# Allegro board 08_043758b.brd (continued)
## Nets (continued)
GND: C1.2(N2) C2.2(N2) C3.2(N2) C4.2(N2) C5.2(N2) C6.2(N2) C7.1(N1) C8.2(N2) C9.2(N2) C10.2(N2) C11.2(N2) C12.2(N2) C13.2(N2) C14.2(N2) C15.2(N2) C16.2(N2) C17.2(N2) C18.2(N2) C19.2(N2) C20.2(N2) C21.2(N2) C22.2(N2) C23.2(N2) C24.2(N2) C25.2(N2) C26.2(N2) C27.2(N2) C28.2(N2) C29.2(N2) C30.2(N2) C31.2(N2) C32.2(N2) C33.2(N2) C34.2(N2) C35.2(N2) C36.2(N2) C37.2(N2) C38.2(N2) C39.2(N2) C40.2(N2) C41.2(N2) C42.2(N2) C43.2(N2) C44.2(N2) C45.2(N2) C46.2(N2) C47.2(N2) C48.2(N2) C49.2(N2) C50.2(N2) C51.2(N2) C52.2(N2) C53.2(N2) C54.2(N2) C55.2(N2) C56.2(N2) C57.2(N2) C58.2(N2) C59.2(N2) C60.2(N2) C61.2(N2) C62.1(N1) C63.1(N1) C64.2(N2) C65.2(N2) C66.2(N2) C67.2(N2) C68.2(N2) C69.2(N2) C70.2(N2) C71.2(N2) C72.2(N2) C73.2(N2) C74.2(N2) C75.2(N2) C76.2(N2) C77.2(N2) C78.2(N2) C79.2(N2) C80.2(N2) C81.2(N2) C82.2(N2) C83.2(N2) C84.2(N2) C85.2(N2) C86.2(N2) C87.2(N2) C88.2(N2) C89.2(N2) C90.2(N2) C91.2(N2) C92.2(N2) C94.2(N2) C95.2(N2) C96.2(N2) C97.2(N2) C99.1(N1) C100.2(N2) C101.2(N2) C102.2(N2) C103.2(N2) C104.2(N2) C105.2(N2) C106.2(N2) C107.2(N2) C108.2(N2) C109.2(N2) C110.2(N2) C111.2(N2) C112.2(N2) C113.2(N2) C114.2(N2) C115.2(N2) C116.2(N2) C117.2(N2) C118.2(N2) C119.2(N2) C120.2(N2) C121.2(N2) C122.2(N2) C124.2(N2) C125.1(N1) C126.1(N1) C127.2(N2) C128.2(N2) C129.1(N1) C130.2(N2) C135.2(N2) C136.2(N2) C137.2(N2) C138.2(N2) C139.1(N1) C140.2(N2) C141.2(N2) C142.1(N1) C143.1(N1) C145.2(N2) C146.2(N2) C147.1(N1) C148.2(N2) C149.2(N2) C150.2(N2) C151.2(N2) C152.2(N2) C153.2(N2) C154.2(N2) C155.2(N2) C156.2(N2) C157.2(N2) C158.2(N2) C159.2(N2) C160.2(N2) C161.2(N2) C162.2(N2) C163.1(N1) C164.2(N2) C165.2(N2) C166.1(N1) C167.2(N2) C168.2(N2) C169.2(N2) C170.2(N2) C173.2(N2) C174.2(N2) C178.2(N2) D1.A(P) D2.A(P) D3.A(P) E6.1(N1) GND.1 GND#2.1 GND#3.1 GND#4.1 L7.3(N3) P1.7(N4) P1.9(N5) Q1.2(S) Q4.2(S) R2.1(N1) R3.1(N1) R9.2(N2) R15.2(N2) R40.2(N2) R42.2(N2) R49.1(N1) R53.1(N1) R54.2(N2) R61.1(N1) R63.2(N2) R65.1(N1) R72.2(N2) R75.2(N2) R77.2(N2) R90.2(N2) R91.2(N2) R116.2(N2) R119.2(N2) R120.2(N2) R121.2(N2) R165.2(N2) RX1A.2(SH1) RX1A.3(SH2) RX1A.4(SH3) RX1A.5(SH4) S1.3(N3) S1.4(N4) T1.1(NC1) T1.2(PRI) T1.5(NC2) T5.1(NC1) T5.2(PRI) T5.5(NC2) TX1A.2(SH1) TX1A.3(SH2) TX1A.4(SH3) TX1A.5(SH4) U1.6(GND) U1.PAD U2.A9(VSS_1) U2.B1(VSSQ_1) U2.B3(VSS_2) U2.B9(VSSQ_2) U2.D1(VSSQ_3) U2.D8(VSSQ_4) U2.E1(VSS_3) U2.E2(VSSQ_5) U2.E8(VSSQ_6) U2.F9(VSSQ_7) U2.G1(VSSQ_8) U2.G8(VSS_4) U2.G9(VSSQ_9) U2.J2(VSS_5) U2.J8(VSS_6) U2.M1(VSS_7) U2.M9(VSS_8) U2.P1(VSS_9) U2.P9(VSS_10) U2.T1(VSS_11) U2.T9(VSS_12) U3.5(GND) U3.6(PGND_1) U3.7(PGND_2) U3.8(PGND_3) U3.PAD U4.A1(GND_1) U4.A11(GND_2) U4.B8(GND_3) U4.C5(GND_4) U4.C15(GND_5) U4.D2(GND_6) U4.D12(GND_7) U4.E5(GND_8) U4.E7(GND_9) U4.E8(RSVDGND) U4.E9(GND_10) U4.F10(GND_11) U4.G3(GND_12) U4.G5(GND_13) U4.G13(GND_14) U4.H6(GND_15) U4.H8(VN_0) U4.H10(GND_16) U4.J5(GND_17) U4.J9(GND_18) U4.K4(GND_19) U4.K7(GND_20) U4.K10(GND_21) U4.K14(GND_22) U4.L1(GND_23) U4.L5(GND_24) U4.L11(GND_25) U4.M8(GND_26) U4.N5(GND_27) U4.N15(GND_28) U4.P2(GND_29) U4.P12(GND_30) U4.R9(GND_31) U5.A1(RX2A_N) U5.A2(RX2A_P) U5.A4(VSSA_1) U5.A5(TX_MON2) U5.A6(VSSA_2) U5.A12(VSSA_3) U5.B1(VSSA_4) U5.B2(VSSA_5) U5.B12(VSSA_6) U5.C1(RX2C_P) U5.C2(VSSA_7) U5.C4(TEST/ENABLE) U5.C7(VSSA_8) U5.C8(VSSA_9) U5.C9(VSSA_10) U5.C10(VSSA_11) U5.C11(VSSA_12) U5.C12(VSSA_13) U5.D1(RX2C_N) U5.D12(VSSD_1) U5.E1(RX2B_P) U5.F1(RX2B_N) U5.F3(VSSA_14) U5.F7(VSSD_2) U5.F9(VSSD_3) U5.F11(VSSD_4) U5.G1(VSSA_15) U5.G10(FB_CLK_N) U5.G12(VSSD_5) U5.H1(RX1B_P) U5.H2(VSSA_16) U5.H3(VSSA_17) U5.H5(VSSA_18) U5.H6(VSSA_19) U5.H7(VSSD_6) U5.H9(TX_FRAME_N) U5.H10(VSSD_7) U5.J1(RX1B_N) U5.J2(VSSA_20) U5.K1(RX1C_P) U5.K2(VSSA_21) U5.K12(VSSD_8) U5.L1(RX1C_N) U5.L2(VSSA_22) U5.L3(VSSA_23) U5.L7(VSSA_24) U5.L8(VSSA_25) U5.L9(VSSA_26) U5.L10(VSSA_27) U5.L11(VSSA_28) U5.L12(VSSA_29) U5.M4(VSSA_30) U5.M5(TX_MON1) U5.M6(VSSA_31) U6.1(GND) U6.19(PGND4) U6.20(PGND3) U6.21(PGND2) U6.22(PGND1) U6.PAD U7.6(GND) U7.PAD U10.4(GND) U11.4(GND) U12.3(GND) U12.PAD U13.B3(VSS) U14.4(PGND) U14.8(GND) U14.PAD U15.PAD(GND_FLAG) Y1.2(GND) Y2.2(GND) Y3.2(GND)
PGND: C171.2(N2) C172.2(N2) L7.4(N4) P2.5(N5) P3.5(N5) Q2.2(S) R55.2(N2) R58.2(N2) R67.2(N2) R69.2(N2) U8.C1(GND) U9.C1(GND) U16.B2(GND)
VCCPINT: C17.1(N1) C19.1(N1) C20.1(N1) C21.1(N1) C64.1(N1) C66.1(N1) C68.1(N1) C70.1(N1) C71.1(N1) C72.1(N1) C73.1(N1) C74.1(N1) C75.1(N1) L4.2(N2) R7.2(N2) U4.E10(VCCINT_1) U4.F9(VCCINT_2) U4.G6(VCCPINT_1) U4.G10(VCCINT_3) U4.H5(VCCPINT_2) U4.J10(VCCINT_4) U4.K5(VCCPINT_3) U4.L10(VCCINT_5) UNK1P0V.1
VCCPLL: C85.1(N1) C178.1(N1) E1.2(N2) U4.F5(VCCPLL)
VDD33_USB: C165.1(N1) U15.20(VDD33)
VDD_INTERFACE: C32.1(N1) C33.1(N1) C38.1(N1) C43.1(N1) C44.1(N1) C45.1(N1) E4.2(N2) U5.H12(VDD_INTERFACE)
VDDA1P1_RX_VCO: C125.2(N2) R51.2(N2) U5.G2(RX_VCO_LDO_OUT) U5.G3(VDDA1P1_RX_VCO)
VIN: C8.1(N1) C9.1(N1) C11.1(N1) C62.2(N2) C135.1(N1) C136.1(N1) C137.1(N1) C138.1(N1) C157.1(N1) C164.1(N1) C167.1(N1) C169.1(N1) DS1.A(P) DS2.A(P) E2.1(N1) Q3.2(S) R1.2(N2) R6.1(N1) R56.1(N1) R59.2(N2) R80.1(N1) R81.1(N1) R85.1(N1) R221.1(N1) R222.1(N1) U3.12(PVIN_1) U3.13(PVIN_2) U6.14(VIN4) U6.15(VIN5) U6.16(VIN6) U6.25(VIN3) U6.26(VIN2) U6.27(VIN1) U11.8(VCCB) U14.10(VDD) U15.21(VBAT)
VIN_5V_USB: L7.1(N1) U8.A1(OUT1) U8.B1(OUT2) U9.A1(OUT1) U9.B1(OUT2)
VIN_5V_USB_DATA: F1.2(N2) P2.1(N1) R70.1(N1) U9.A2(IN1) U9.B2(IN2)
VIN_5V_USB_POWER: P3.1(N1) R66.1(N1) R68.1(N1) U8.A2(IN1) U8.B2(IN2) U16.A1(VIN)
1P3_SUPPLY_A: C14.1(N1) C15.1(N1) C16.1(N1) C18.1(N1) C23.1(N1) C24.1(N1) C28.1(N1) C29.1(N1) C34.1(N1) C35.1(N1) C39.1(N1) C40.1(N1) U5.B9(VDDA1P3_TX_LO) U5.B10(VDDA1P3_TX_VCO_LDO) U5.E2(VDDA1P3_RX_LO) U5.F2(VDDA1P3_RX_VC_LDO) U5.J3(VDDA1P3_RX_SYNTH) U5.K3(VDDA1P3_TX_SYNTH) U7.9(SENSE) U7.10(VOUT1) U7.11(VOUT2) U7.12(VOUT3) U7.13(VOUT4) U7.14(VOUT5) UNK1P3V_A.1
1P3_SUPPLY_B: C3.1(N1) C4.1(N1) C5.1(N1) C6.1(N1) C26.1(N1) C27.1(N1) C30.1(N1) C31.1(N1) C36.1(N1) C37.1(N1) C41.1(N1) C42.1(N1) C129.2(N2) C130.1(N1) E3.2(N2) L8.1(N1) L9.1(N1) U1.9(SENSE) U1.10(VOUT1) U1.11(VOUT2) U1.12(VOUT3) U1.13(VOUT4) U1.14(VOUT5) U5.A7(TX2A_N) U5.A8(TX2A_P) U5.A9(TX2B_N) U5.A10(TX2B_P) U5.B8(VDD_GPO) U5.D2(VDDA1P3_RX_RF) U5.D3(VDDA1P3_RX_TX) U5.E3(VDDA1P3_TX_LO_BUFFER) U5.F12(VDDS1P3_DIG) U5.K4(VDDAP3_BB) U5.M9(TX1B_P) U5.M10(TX1B_N) UNK1P3V_B.1
1P8V_CLK: C121.1(N1) C122.1(N1) C170.1(N1) U12.1(VOUT) UNK1P8V_CLK.1 Y3.4(VDD)
AD9363_AUXADC: ADC.1(N1) U5.L5(AUXADC)
AD9363_AUXDAC1: DAC1.1(N1) U5.B3(AUXDAC1)
AD9363_AUXDAC2: DAC2.1(N1) U5.C3(AUXDAC2)
AD9363_GPO_0: GPO0.1(N1) U5.B7(GPO_0)
AD9363_GPO_1: GPO1.1(N1) U5.B6(GPO_1)
AD9363_GPO_2: GPO2.1(N1) U5.B5(GPO_2)
AD9363_GPO_3: GPO3.1(N1) U5.B4(GPO_3)
ADM1177_SCL: R81.2(N2) U10.6(SCL) U11.7(SCLB)
ADM1177_SDA: R80.2(N2) U10.7(SDA) U11.6(SDAB)
ADP2114_VIN: C141.1(N1) R56.2(N2) U6.4(SCFG) U6.8(VDD) U6.10(V2SET) U6.31(V1SET)
COMP_1P8V: C142.2(N2) R60.1(N1) U6.2(COMP1)
COMP_1P35V: C143.2(N2) C144.1(N1) U6.7(COMP2)
CTRL_IN0: U4.F13(IO_L3P_T0_DQS_AD1P_35) U5.C5(CTRL_IN0)
CTRL_IN1: U4.F14(IO_L3N_T0_DQS_AD1N_35) U5.C6(CTRL_IN1)
CTRL_IN2: U4.G15(IO_L5P_T0_AD9P_35) U5.D6(CTRL_IN2)
CTRL_IN3: U4.F15(IO_L5N_T0_AD9N_35) U5.D5(CTRL_IN3)
DDR3_A0: R16.1(N1) U2.N3(A0) U4.P1(PS_DDR_A0_502)
DDR3_A1: R22.1(N1) U2.P7(A1) U4.N1(PS_DDR_A1_502)
DDR3_A2: R17.1(N1) U2.P3(A2) U4.M1(PS_DDR_A2_502)
DDR3_A3: R23.1(N1) U2.N2(A3) U4.M4(PS_DDR_A3_502)
DDR3_A4: R18.1(N1) U2.P8(A4) U4.P3(PS_DDR_A4_502)
DDR3_A5: R24.1(N1) U2.P2(A5) U4.P4(PS_DDR_A5_502)
DDR3_A6: R19.1(N1) U2.R8(A6) U4.P5(PS_DDR_A6_502)
DDR3_A7: R25.1(N1) U2.R2(A7) U4.M5(PS_DDR_A7_502)
DDR3_A8: R20.1(N1) U2.T8(A8) U4.P6(PS_DDR_A8_502)
DDR3_A9: R26.1(N1) U2.R3(A9) U4.N4(PS_DDR_A9_502)
DDR3_A10: R21.1(N1) U2.L7(A10/AP) U4.J1(PS_DDR_A10_502)
DDR3_A11: R27.1(N1) U2.R7(A11) U4.L2(PS_DDR_A11_502)
DDR3_A12: R28.1(N1) U2.N7(A12/BC#) U4.M2(PS_DDR_A12_502)
DDR3_A13: R34.1(N1) U2.T3(A13) U4.K2(PS_DDR_A13_502)
DDR3_A14: R29.1(N1) U2.T7(A14) U4.K1(PS_DDR_A14_502)
DDR3_BA0: R35.1(N1) U2.M2(BA0) U4.M6(PS_DDR_BA0_502)
DDR3_BA1: R30.1(N1) U2.N8(BA1) U4.R1(PS_DDR_BA1_502)
DDR3_BA2: R36.1(N1) U2.M3(BA2) U4.N6(PS_DDR_BA2_502)
DDR3_CAS#: R32.1(N1) U2.K3(CAS#) U4.R5(PS_DDR_CAS_B_502)
DDR3_CK_N: R142.2(N2) U2.K7(CK#) U4.N2(PS_DDR_CKN_502)
DDR3_CK_P: R142.1(N1) U2.J7(CK) U4.N3(PS_DDR_CKP_502)
DDR3_CKE: R38.1(N1) U2.K9(CKE) U4.L3(PS_DDR_CKE_502)
DDR3_CS#: R39.1(N1) U2.L2(CS#) U4.R2(PS_DDR_CS_B_502)
DDR3_DM0: U2.E7(LDM) U4.B1(PS_DDR_DM0_502)
DDR3_DM1: U2.D3(UDM) U4.D3(PS_DDR_DM1_502)
DDR3_DQ0: U2.E3(DQ0) U4.D4(PS_DDR_DQ0_502)
DDR3_DQ1: U2.F7(DQ1) U4.A2(PS_DDR_DQ1_502)
DDR3_DQ2: U2.F2(DQ2) U4.C4(PS_DDR_DQ2_502)
DDR3_DQ3: U2.F8(DQ3) U4.C1(PS_DDR_DQ3_502)
DDR3_DQ4: U2.H3(DQ4) U4.B4(PS_DDR_DQ4_502)
DDR3_DQ5: U2.H8(DQ5) U4.A4(PS_DDR_DQ5_502)
DDR3_DQ6: U2.G2(DQ6) U4.C3(PS_DDR_DQ6_502)
DDR3_DQ7: U2.H7(DQ7) U4.A3(PS_DDR_DQ7_502)
DDR3_DQ8: U2.D7(DQ8) U4.E1(PS_DDR_DQ8_502)
DDR3_DQ9: U2.C3(DQ9) U4.D1(PS_DDR_DQ9_502)
DDR3_DQ10: U2.C8(DQ10) U4.E2(PS_DDR_DQ10_502)
DDR3_DQ11: U2.C2(DQ11) U4.E3(PS_DDR_DQ11_502)
DDR3_DQ12: U2.A7(DQ12) U4.F3(PS_DDR_DQ12_502)
DDR3_DQ13: U2.A2(DQ13) U4.G1(PS_DDR_DQ13_502)
DDR3_DQ14: U2.B8(DQ14) U4.H1(PS_DDR_DQ14_502)
DDR3_DQ15: U2.A3(DQ15) U4.H2(PS_DDR_DQ15_502)
DDR3_DQS0_N: U2.G3(LDQS#) U4.B2(PS_DDR_DQS_N0_502)
DDR3_DQS0_P: U2.F3(LDQS) U4.C2(PS_DDR_DQS_P0_502)
DDR3_DQS1_N: U2.B7(UDQS#) U4.F2(PS_DDR_DQS_N1_502)
DDR3_DQS1_P: U2.C7(UDQS) U4.G2(PS_DDR_DQS_P1_502)
DDR3_ODT: R33.1(N1) U2.K1(ODT) U4.K3(PS_DDR_ODT_502)
DDR3_RAS#: R37.1(N1) U2.J3(RAS#) U4.R6(PS_DDR_RAS_B_502)
DDR3_RST#: R42.1(N1) U2.T2(RESET#) U4.L4(PS_DDR_DRST_B_502)
DDR3_WE#: R31.1(N1) U2.L3(WE#) U4.R3(PS_DDR_WE_B_502)
FB0: R2.2(N2) R4.1(N1) U3.4(FB)
FB_1P8V: R64.1(N1) R65.2(N2) U6.32(FB1)
FB_1P35V: R62.2(N2) R63.1(N1) U6.9(FB2)
IO_02_34_AD9361_CLKOUT: AD9361_CLKOUT.1(N1) U4.P8(IO_L23P_T3_34) U5.J6(CLK_OUT)
IO_02_34_AD9361_RST: U4.P9(IO_L23N_T3_34) U5.K5(RESETB)
IO_L01_34_FB_CLK: U4.P10(IO_L24P_T3_34) U5.F10(FB_CLK_P)
IO_L01_34_RX_D0: U4.H14(IO_L3N_T0_DQS_34) U5.K11(P1_D0/RX_D0_N)
IO_L01_34_RX_D1: U4.J13(IO_L5P_T0_34) U5.J12(P1_D1/RX_D0_P)
IO_L02_34_RX_D2: U4.G14(IO_L3P_T0_DQS_PUDC_B_34) U5.K10(P1_D2/RX_D1_N)
IO_L02_34_RX_D3: U4.H13(IO_L2N_T0_34) U5.J11(P1_D3/RX_D1_P)
IO_L03_34_RX_D4: U4.G12(IO_L2P_T0_34) U5.K9(P1_D4/RX_D2_N)
IO_L03_34_RX_D5: U4.H12(IO_L1N_T0_34) U5.J10(P1_D5/RX_D2_P)
IO_L04_34_RX_D6: U4.G11(IO_L1P_T0_34) U5.K8(P1_D6/RX_D3_N)
IO_L04_34_RX_D7: U4.J14(IO_L5N_T0_34) U5.J9(P1_D7/RX_D3_P)
IO_L05_34_RX_D8: U4.J15(IO_L4P_T0_34) U5.K7(P1_D8/RX_D4_N)
IO_L05_34_RX_D9: U4.K15(IO_L4N_T0_34) U5.J8(P1_D9/RX_D4_P)
IO_L06_34_RX_D10: U4.H11(IO_L6P_T0_34) U5.J7(P1_D10/RX_D5_N)
IO_L06_34_RX_D11: U4.J11(IO_L6N_T0_VREF_34) U5.H8(P1_D11/RX_D5_P)
IO_L07_34_RX_FRAME: U4.N13(IO_L7P_T1_34) U5.G8(RX_FRAME_P)
IO_L08_34_CTRL_OUT0: U4.L15(IO_L8P_T1_34) U5.D4(CTRL_OUT0)
IO_L08_34_CTRL_OUT1: U4.M15(IO_L8N_T1_34) U5.E4(CTRL_OUT1)
IO_L09_34_TX_FRAME: U4.L14(IO_L9P_T1_DQS_34) U5.G9(TX_FRAME_P)
IO_L10_34_EN_AGC: U4.L13(IO_L10N_T1_34) U5.G5(EN_AGC)
IO_L11_34_ENABLE: U4.K12(IO_L11N_T1_SRCC_34) U5.G6(ENABLE)
IO_L11_34_TXNRX: U4.K11(IO_L11P_T1_SRCC_34) U5.H4(TXNRX)
IO_L12_MRCC_34_DATA_CLK: U4.L12(IO_L12P_T1_MRCC_34) U5.G11(DATA_CLK_P)
IO_L13_34_CTRL_OUT2: U4.N11(IO_L13P_T2_MRCC_34) U5.E5(CTRL_OUT2)
IO_L13_34_CTRL_OUT3: U4.N12(IO_L13N_T2_MRCC_34) U5.E6(CTRL_OUT3)
IO_L15_34_TX_D0: U4.P15(IO_L15P_T2_DQS_34) U5.E12(P0_D0/TX_D0_N)
IO_L15_34_TX_D1: U4.R13(IO_L17N_T2_34) U5.D11(P0_D1/RX_D0_P)
IO_L16_34_TX_D2: U4.R15(IO_L15N_T2_DQS_34) U5.E11(P0_D2/TX_D1_N)
IO_L16_34_TX_D3: U4.P11(IO_L16P_T2_34) U5.D10(P0_D3/TX_D1_P)
IO_L17_34_TX_D4: U4.R11(IO_L16N_T2_34) U5.E10(P0_D4/TX_D2_N)
IO_L17_34_TX_D5: U4.R12(IO_L17P_T2_34) U5.D9(P0_D5/TX_D2_P)
IO_L18_34_TX_D6: U4.P14(IO_L18N_T2_34) U5.E9(P0_D6/TX_D3_N)
IO_L18_34_TX_D7: U4.P13(IO_L18P_T2_34) U5.D8(P0_D7/TX_D3_P)
IO_L19_34_TX_D8: U4.N9(IO_L19N_T3_VREF_34) U5.E8(P0_D8/TX_D4_N)
IO_L19_34_TX_D9: U4.M9(IO_L19P_T3_34) U5.D7(P0_D9/TX_D4_P)
IO_L20_34_TX_D10: U4.R8(IO_L20N_T3_34) U5.F8(P0_D10/TX_D5_N)
IO_L20_34_TX_D11: U4.R7(IO_L20P_T3_34) U5.E7(P0_D11/TX_D5_P)
IO_L21_34_CTRL_OUT4: U4.M10(IO_L21P_T3_DQS_34) U5.F6(CTRL_OUT4)
IO_L21_34_CTRL_OUT5: U4.M11(IO_L21N_T3_DQS_34) U5.F5(CTRL_OUT5)
IO_L22_34_CTRL_OUT6: U4.N7(IO_L22P_T3_34) U5.F4(CTRL_OUT6)
IO_L22_34_CTRL_OUT7: U4.N8(IO_L22N_T3_34) U5.G4(CTRL_OUT7)
IO_L23_35_SPI_CLK: U4.E11(IO_L2P_T0_AD8P_35) U5.J5(SPI_CLK)
IO_L23_35_SPI_ENB: U4.E12(IO_L2N_T0_AD8N_35) U5.K6(SPI_ENB)
IO_L24_35_SPI_DI: U4.E13(IO_L1N_T0_AD0N_35) U5.J4(SPI_DI)
IO_L24_35_SPI_DO: U4.F12(IO_L1P_T0_AD0P_35) U5.L6(SPI_DO)
JTAG_TCK: P1.4(N2) TCK.1(N1) U4.G9(TCK_0)
JTAG_TDI: P1.8(N4) TDI.1(N1) U4.L7(TDI_0)
JTAG_TDO: P1.6(N3) TDO.1(N1) U4.L8(TDO_0)
JTAG_TMS: P1.2(N1) TMS.1(N1) U4.L9(TMS_0)
PG_1P0V: R6.2(N2) R86.1(N1) U3.16(PGOOD)
PG_1P3V: C47.1(N1) PG_1P3V.1(N1) R13.2(N2) R15.1(N1) U1.5(PG) U4.C9(PS_POR_B_500) U7.5(PG) U12.4(EN)
PG_1P8V: R59.1(N1) U6.13(EN2) U6.29(PGOOD1)
PG_1P35V: R50.1(N1) U1.4(EN) U6.12(PGOOD2) U7.4(EN)
PL_GPIO0: L10P.1(N1) U4.K13(IO_L10P_T1_34)
PL_GPIO1: L12N.1(N1) U4.M12(IO_L12N_T1_MRCC_34)
PL_GPIO2: L24N.1(N1) U4.R10(IO_L24N_T3_34)
PS-SRST#: R74.2(N2) U4.B11(PS_SRST_B_501) U13.A4(RESET#/DNU)
PS_GPIO0: MIO0.1(N1) U4.D8(PS_MIO0_500)
PS_GPIO1: MIO10.1(N1) U4.B10(PS_MIO11_500)
PS_GPIO2: MIO11.1(N1) U4.D6(PS_MIO10_500)
PS_GPIO3: MIO09.1(N1) U4.B5(PS_MIO9_500)
PS_GPIO4: MIO53.1(N1) U4.C13(PS_MIO53_501)
PS_GPIO5: MIO49.1(N1) U4.D13(PS_MIO49_501)
PS_GPIO6: MIO48.1(N1) U4.B12(PS_MIO48_501)
PS_MIO01_500_QSPI0_SS_B: R14.2(N2) U4.A5(PS_MIO1_500) U13.C2(S#)
PS_MIO02_500_QSPI0_IO0: R120.1(N1) U4.A8(PS_MIO2_500) U13.D3(DQ0)
PS_MIO03_500_QSPI0_IO1: R119.1(N1) U4.A7(PS_MIO3_500) U13.D2(DQ1)
PS_MIO04_500_QSPI0_IO2: R121.1(N1) U4.C8(PS_MIO4_500) U13.C4(W#DQ2)
PS_MIO05_500_QSPI0_IO3: JTAG_BOOT.1(N1) P1.5(N3) R122.1(N1) U4.A9(PS_MIO5_500) U13.D4(DQ3)
PS_MIO06_500_QSPI0_SCLK: R116.1(N1) U4.A10(PS_MIO6_500) U13.B2(C)
PS_MIO07_500_USB_RESET_B: R76.2(N2) U4.A12(PS_MIO52_501) U15.27(RESETB)
PS_MIO28_501_USB0_D4: U4.A15(PS_MIO28_501) U15.7(DATA4)
PS_MIO29_501_USB0_DIR: U4.D11(PS_MIO29_501) U15.31(DIR)
PS_MIO30_501_USB0_STP: U4.B15(PS_MIO30_501) U15.29(STP)
PS_MIO31_501_USB0_NXT: U4.C12(PS_MIO31_501) U15.2(NXT)
PS_MIO32_501_USB0_D0: U4.E15(PS_MIO32_501) U15.3(DATA0)
PS_MIO33_501_USB0_D1: U4.C11(PS_MIO33_501) U15.4(DATA1)
PS_MIO34_501_USB0_D2: U4.D15(PS_MIO34_501) U15.5(DATA2)
PS_MIO35_501_USB0_D3: U4.A14(PS_MIO35_501) U15.6(DATA3)
PS_MIO36_501_USB0_CLK: U4.B14(PS_MIO36_501) U15.1(CLKOUT)
PS_MIO37_501_USB0_D5: U4.C14(PS_MIO37_501) U15.9(DATA5)
PS_MIO38_501_USB0_D6: U4.A13(PS_MIO38_501) U15.10(DATA6)
PS_MIO39_501_USB0_D7: U4.D14(PS_MIO39_501) U15.13(DATA7)
PWR_CLK: R5.2(N2) R89.2(N2) R90.1(N1) U3.1(SYNC)
RX1A_N: C133.2(N2) U5.M2(RX1A_N)
RX1A_P: C134.2(N2) U5.M1(RX1A_P)
SCL: R79.2(N2) U4.M14(IO_L9N_T1_DQS_34) U11.2(SCLA)
SDA: R78.2(N2) U4.N14(IO_L7N_T1_34) U11.3(SDAA)
SYNC: L4.1(N1) U3.9(SW_1) U3.10(SW_2) U3.11(SW_3)
TX1A_N: C131.1(N1) L8.2(N2) U5.M8(TX1A_N)
TX1A_P: C132.1(N1) L9.2(N2) U5.M7(TX1A_P)
TX_VCO_1P1V_SUPPLY: C128.1(N1) R52.1(N1) U5.A11(VDDA1P1_TX_VCO) U5.B11(TX_VCO_LDO_OUT)
UART_RX: P1.1(N1) RX.1(N1) U4.C6(PS_MIO13_500)
UART_TX: P1.3(N2) TX.1(N1) U4.B7(PS_MIO12_500)
UNNAMED_2_ADM7160V2_I254_VIN: C173.1(N1) E2.2(N2) U12.6(VIN)
UNNAMED_2_ADP1754_I93_SS: C2.1(N1) U1.7(SS)
UNNAMED_2_ADP1754_I233_SS: C12.1(N1) U7.7(SS)
UNNAMED_2_ADP2164_I29_EN: C13.1(N1) R1.1(N1) R5.1(N1) R10.1(N1) U3.3(TRK) U3.14(VIN) U3.15(EN)
UNNAMED_2_ADP2164_I29_RT: R3.2(N2) R10.2(N2) U3.2(RT)
UNNAMED_2_FERRITE_I303_N1: E3.1(N1) VDD_GPO.1(N1)
UNNAMED_2_RES_I251_N2: R4.2(N2) R7.1(N1)
UNNAMED_3_ICXC7Z010_I16_PSCLK50: R12.2(N2) U4.C7(PS_CLK_500)
UNNAMED_3_ICXC7Z010_I16_PSMIO75: R83.2(N2) U4.D9(PS_MIO7_500)
UNNAMED_3_ICXC7Z010_I16_PSMIO85: R84.1(N1) U4.B6(PS_MIO8_500)
UNNAMED_3_RES_I2_N1: R8.2(N2) R9.1(N1) Y2.1(STANDBY)
UNNAMED_3_RES_I48_N1: R12.1(N1) Y2.3(OUTPUT)
UNNAMED_4_ICMT41K256M16_I98_ZQ: R165.1(N1) U2.L8(ZQ)
UNNAMED_4_ICTPS51206_I44_S3: R222.2(N2) U14.7(S3)
UNNAMED_4_ICTPS51206_I44_S5: R221.2(N2) U14.9(S5)
UNNAMED_4_ICTPS51206_I44_VLDOIN: R44.2(N2) U14.2(VLDOIN)
UNNAMED_4_ICTPS51206_I44_VTTSNS: C80.1(N1) R43.2(N2) U14.5(VTTSNS)
UNNAMED_4_ICXC7Z010_I26_PSDDR_1: R40.1(N1) U4.H3(PS_DDR_VRP_502)
UNNAMED_4_ICXC7Z010_I26_PSDDRVR: R41.1(N1) U4.J3(PS_DDR_VRN_502)
UNNAMED_5_CAP_I17_N1: C93.1(N1) C98.1(N1) E5.2(N2) U4.F7(VCCADC_0)
UNNAMED_5_CAP_I17_N2: C93.2(N2) C98.2(N2) E6.2(N2) U4.F6(CFGBVS_0) U4.F8(GNDADC_0) U4.G8(VREFN_0) U4.H7(VREFP_0) U4.J7(DXP_0)
UNNAMED_5_DIOLED_I60_N: DS1.C(N) R48.1(N1)
UNNAMED_5_DIOLED_I62_N: DS2.C(N) R87.1(N1)
UNNAMED_5_ICXC7Z010_I13_DONE0: Q1.1(G) U4.M7(DONE_0)
UNNAMED_5_ICXC7Z010_I13_INITB0: R47.1(N1) U4.D5(INIT_B_0)
UNNAMED_5_ICXC7Z010_I13_PROGRAM: R46.1(N1) U4.K6(PROGRAM_B_0)
UNNAMED_5_ICXC7Z010_I13_VCCBATT: R45.2(N2) U4.E6(VCCBATT_0)
UNNAMED_5_ICXC7Z010_I13_VP0: R11.2(N2) R91.1(N1) U4.G7(VP_0)
UNNAMED_5_RES_I61_N2: Q1.3(D) R48.2(N2)
UNNAMED_5_RES_I63_N2: Q4.3(D) R87.2(N2)
UNNAMED_7_AD9363_I13_RBIAS: R49.2(N2) U5.L4(RBIAS)
UNNAMED_7_AD9363_I13_XTALN: C123.2(N2) C124.1(N1) U5.M12(XTALN)
UNNAMED_7_CAP_I22_N2: C126.2(N2) R51.1(N1)
UNNAMED_7_CAP_I30_N1: C127.1(N1) R52.2(N2)
UNNAMED_7_CAP_I39_N2: C132.2(N2) T5.4(SEC)
UNNAMED_7_CAP_I40_N2: C131.2(N2) T5.6(SEC_DOT)
UNNAMED_7_CAP_I51_N1: C134.1(N1) T1.4(SEC)
UNNAMED_7_CAP_I52_N1: C133.1(N1) T1.6(SEC_DOT)
UNNAMED_7_CAP_I53_N1: C123.1(N1) Y3.3(OUT)
UNNAMED_7_CNBNC5P_I57_CNTR: RX1A.1(CNTR) T1.3(PRI_DOT)
UNNAMED_7_CNBNC5P_I58_CNTR: T5.3(PRI_DOT) TX1A.1(CNTR)
UNNAMED_9_ADM1177_I23_GATE: Q3.1(G) U10.10(GATE)
UNNAMED_9_ADM1177_I23_ON: R71.2(N2) R72.1(N1) U10.3(ON)
UNNAMED_9_ADM1177_I23_SENSE: Q3.3(D) R73.2(N2) U10.2(SENSE)
UNNAMED_9_ADM1177_I23_SS: C155.1(N1) U10.9(SS)
UNNAMED_9_ADM1177_I23_TIMER: C156.1(N1) U10.5(TIMER)
UNNAMED_9_ADM1177_I23_VCC: D3.C(N) L7.2(N2) R71.1(N1) R73.1(N1) U10.1(VCC)
UNNAMED_9_ADP198_I329_VOUT: C171.1(N1) C172.1(N1) F1.1(N1) R88.1(N1) U16.A2(VOUT)
UNNAMED_9_ADP2114_I196_EN1: R85.2(N2) R86.2(N2) U6.28(EN1)
UNNAMED_9_ADP2114_I196_FREQ: R53.2(N2) U6.3(FREQ)
UNNAMED_9_ADP2114_I196_OPCFG: R54.1(N1) U6.6(OPCFG)
UNNAMED_9_ADP2114_I196_SS1: C7.2(N2) U6.30(SS1)
UNNAMED_9_ADP2114_I196_SS2: C139.2(N2) U6.11(SS2)
UNNAMED_9_ADP2114_I196_SW1: L3.1(N1) R89.1(N1) U6.23(SW2) U6.24(SW1)
UNNAMED_9_ADP2114_I196_SW3: L2.1(N1) U6.17(SW4) U6.18(SW3)
UNNAMED_9_CAP_I163_N1: C146.1(N1) L3.2(N2) L5.1(N1)
UNNAMED_9_CAP_I214_N2: C147.2(N2) R60.2(N2)
UNNAMED_9_CAP_I224_N2: C144.2(N2) R61.2(N2)
UNNAMED_9_CHOKE4P_I327_N2: D1.C(N) L6.2(N2) P2.3(N3)
UNNAMED_9_CHOKE4P_I327_N3: D2.C(N) L6.3(N3) P2.2(N2)
UNNAMED_9_CN5P3SHLD_I255_N6: P2.SH1(N6) P2.SH2(N7) P2.SH3(N8) R55.1(N1)
UNNAMED_9_CN5P3SHLD_I256_N6: P3.SH1(N6) P3.SH2(N7) P3.SH3(N8) R58.1(N1)
UNNAMED_9_ICNCP339_I277_EN: R68.2(N2) R69.1(N1) U8.C2(EN)
UNNAMED_9_ICNCP339_I278_EN: Q2.3(D) R70.2(N2) U9.C2(EN)
UNNAMED_9_RES_I270_N1: Q2.1(G) R66.2(N2) R67.1(N1)
UNNAMED_11_ICUSB3320C_I29_RBIAS: R77.1(N1) U15.24(RBIAS)
UNNAMED_11_ICUSB3320C_I29_REFCL: R82.1(N1) U15.26(REFCLK)
UNNAMED_11_RES_I67_N2: R82.2(N2) Y1.3(OUTPUT)
USB_ID: P2.4(N4) U15.23(ID)
USB_OTG_CPEN: U15.17(CPEN) U16.B1(EN)
USB_OTG_N: L6.4(N4) U15.19(DM)
USB_OTG_P: L6.1(N1) U15.18(DP)
USB_VBUS_OTG: R88.2(N2) U15.22(VBUS)
USR_BTN: R57.2(N2) S1.1(N1) U4.B9(PS_MIO14_500)
USR_LED: Q4.1(G) R75.1(N1) U4.D10(PS_MIO15_500)
VTT_0P75: C79.1(N1) C101.1(N1) R16.2(N2) R17.2(N2) R18.2(N2) R19.2(N2) R20.2(N2) R21.2(N2) R22.2(N2) R23.2(N2) R24.2(N2) R25.2(N2) R26.2(N2) R27.2(N2) R28.2(N2) R29.2(N2) R30.2(N2) R31.2(N2) R32.2(N2) R33.2(N2) R34.2(N2) R35.2(N2) R36.2(N2) R37.2(N2) R38.2(N2) R39.2(N2) R43.1(N1) U14.3(VTT)
VTTVREF: C63.2(N2) C81.1(N1) C84.1(N1) C99.2(N2) C102.1(N1) U2.H1(VREFDQ) U2.M8(VREFCA) U4.F4(PS_DDR_VREF0_502) U14.6(VTTREF)

Pads without a net: P3 2 3 4; S1 2 5; U1 8; U2 J1 J9 L1 L9 M7; U5 A3 G7 H11 M3 M11; U6 5; U7 8; U10 8; U11 5; U12 2 5; U13 A2 A3 A5 B1 B5 C1 C3 C5 D1 D5 E1 E2 E3 E4 E5; U15 12 15 16 25; Y1 1; Y3 1

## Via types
v1: diameter 0.508, hole 0.254, TOP to BOTTOM, 784 vias
v2: diameter 0.406, hole 0.203, TOP to BOTTOM, 592 vias

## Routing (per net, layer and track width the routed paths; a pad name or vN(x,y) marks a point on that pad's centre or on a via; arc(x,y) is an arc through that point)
1V8: length 131.4
  TOP w0.203: 50.11,81.09 50.23,80.97
  TOP w0.305: 28.52,81.09 U1.3 U1.2 ; U1.16 U1.15 ; U1.16 26.3,82.36 ; U1.16 25.52,82.79 ; U4.H15 v2(62.87,99.03) ; Y2.4 78.94,106.5 C46.1 80.08,107.07 v1(80.01,107.13) ; U4.A6 v2(68.97,106.83) ; 27.22,81.09 U1.1 ; U1.1 26.79,81.87 ; U1.1 U1.2 ; 49.46,81.09 U7.2 ; U7.2 U7.3 50.11,81.09 ; U7.2 U7.1 ; U4.H4 v2(63.27,108.83) ; 47.89,82.36 U7.16 ; U7.16 U7.15 ; U7.16 47.11,82.79 ; U15.11 v1(84.34,94.19) ; U4.H9 v2(62.47,104.83) ; 27.87,81.09 U1.2 ; 40.07,83.69 C25.1 ; C25.1 40.48,84.15 ; C25.1 40.07,84.6 ; R74.1 73.79,101.66 v1(73.79,101.42) ; C10.1 50.11,80.79 ; C10.1 50.11,79.88 ; C10.1 49.7,80.34 ; U15.30 84.34,101.15 v1(84.33,101.17) ; 28.52,79.88 C1.1 ; C1.1 28.11,80.34 ; C1.1 28.52,80.79 ; U4.D7 v2(66.47,106.43) ; U4.B13 v2(68.07,100.83) ; U4.N10 v2(58.47,103.23) ; v1(85.98,94.18) 85.84,94.32 U15.14 ; U4.P7 v2(57.67,106.43) ; R78.1 64.15,84.92 v1(63.88,84.66) ; U11.1 65.51,87.73 C166.2 64.96,88.72 v1(65.14,88.9) ; U4.G4 v2(64.07,108.83) ; U4.M13 v2(59.27,100.83) ; v1(85.35,101.17) 85.34,101.16 U15.28 ; U15.8 v1(82.64,95.32) ; R47.2 v1(73.66,111.11) ; v1(76.08,110.31) 75.18,110.31 R84.2 ; UNK1V8#2.1 90.05,105.23 ; UNK1V8#2.1 90.81,104.47 ; UNK1V8#2.1 90.05,103.7 ; v1(63.47,87.13) R79.1 ; 48.81,81.09 U7.1 ; U7.1 48.38,81.87 ; U4.F11 v2(64.87,102.43) ; U4.L6 v2(60.87,106.43) ; U4.K8 v2(60.87,105.63) ; U4.J4 v2(61.67,108.83) ; U13.B4 v2(82.15,117.19) ; v1(82.81,101.04) 83.34,100.5 U15.32 ; U4.K9 v2(60.87,104.83) ; Y1.4 86.94,106.43 C163.2 v1(87.51,107.77) ; U4.J6 v2(61.67,107.23) ; U4.J12 v2(61.67,101.63) ; U4.E14 v2(65.67,100.03) ; U4.J8 v2(61.67,105.63) ; U4.C10 v2(67.27,103.23) ; R8.1 v1(81.14,108.79) ; U4.R14 v2(56.87,100.03)
  TOP w0.508: 49.28,122.21 R44.1 ; R44.1 49.84,122.77 ; R44.1 48.72,122.77
  TOP w0.635: E4.1 42.68,84.08 ; E4.1 40.9,84.08 ; E4.1 41.79,83.26 ; C22.1 41.6,82.24 ; C22.1 40.96,82.94 ; C22.1 40.96,81.54
  TOP w0.762: C83.1 49.28,120.6 ; C83.1 48.48,121.45 ; C83.1 48.48,119.74 ; 48.48,116.95 C82.1 ; C82.1 49.28,117.8 ; C82.1 48.48,118.65
  TOP w1.016: 91.66,107.81 L5.2 90.3,107.03
  TOP w1.27: 93.35,105.11 C150.1 ; C150.1 93.35,107.63 ; C150.1 92.29,106.37 ; 92.29,103.32 C149.1 93.35,104.58
  BOTTOM w0.203: 91.46,106.77 v1(91.44,106.75)
  BOTTOM w0.305: R76.1 68.18,100.23 C111.1 ; C78.1 v2(55.16,104.44) C90.1 ; C113.1 v2(68.37,97.52) C107.1 ; C52.1 68.97,107.15 v2(68.97,106.83) 68.97,106.51 C53.1 69.15,105.85 69.47,105.53 R45.1 ; C140.1 v1(85.35,101.17) C168.1 ; R57.1 88.35,107.77 v1(87.51,107.77) ; C69.1 67.88,103.53 67.57,103.53 v2(67.27,103.23) 67.77,102.73 C162.1 ; v2(65.68,97.52) 65.5,97.34 C117.1 ; C110.1 59.36,100.92 v2(59.27,100.83) 59.17,100.73 C118.1 ; C161.1 65.45,100.25 v2(65.67,100.03) ; v1(72.77,104.72) 72.68,104.63 R83.1 ; v1(81.7,105.48) 81.7,104.68 R13.1 ; v2(62.87,99.03) 62.89,99.05 C119.1 ; v1(84.33,101.17) C154.1 ; R14.1 v1(84.08,119.45) ; C48.1 81.77,117.57 v2(82.15,117.19) ; R64.2 93.22,107.13 ; C108.1 v2(55.16,102.83) ; R50.2 v1(88.9,116.91) ; C120.1 57.67,105.73
  BOTTOM w0.406: C50.1 70.58,102.83 v2(70.57,102.83) 70.58,102.82 C159.1 v2(70.58,101.63) C160.1 70.58,100.33 v2(70.57,100.33) 70.57,99.68 C103.1 71.37,99.68 v2(71.37,100.33) ; C51.1 56.83,106.12 57.15,106.43 v2(57.67,106.43) 57.67,105.73 57.67,105.73 ; C67.1 v2(60.47,97.52) C106.1 ; R46.2 59.17,103.93 v2(58.47,103.23) 57.86,103.23 C116.1 ; C112.1 56.87,100.53 v2(56.87,100.03) 56.87,99.52 C114.1 ; C105.1 v2(62.88,97.52) C109.1 ; v2(51.71,104.47) 51.71,103.7 52.11,103.3 C77.1 51.69,102.84 v2(51.69,102.05) ; C111.1 68.07,100.83 v2(68.07,100.83) ; C115.1 v2(65.68,97.52)
  BOTTOM w0.508: v2(52.96,96.59) 53.92,96.59 C104.1 54.28,96.61 v2(55.25,96.61) ; v1(79.12,114.63) R122.2 ; v1(73.66,111.11) 74.46,111.11 R11.1 ; v2(58.17,96.59) 57.22,96.59 C65.1 56.85,96.61 v2(55.88,96.61) ; v1(52.56,109.04) C76.1 52.58,107.61 v1(52.58,106.12)
  BOTTOM w0.635: v1(77.92,110.25) 78.13,110.03 C174.1 78.13,108.23 E1.1 ; C153.1 93.41,105.17 ; C153.1 93.41,103.77 ; C153.1 92.78,104.47 ; 93.41,105.29 C152.1 ; C152.1 92.78,105.99 ; C152.1 93.41,106.69 ; v1(76.84,115.77) 75.89,115.77 E5.1 75.57,116.15 76.2,116.79 v1(76.84,116.79)
  BOTTOM w0.762: 73.79,101.94 C49.1 ; C49.1 73.79,104.45 ; C49.1 72.74,103.2 ; 73.79,101.03 C158.1 72.74,99.77
  vias: v1(27.18,80.21) v1(27.18,79.58) v1(27.18,78.94) v1(27.82,80.21) v1(27.82,79.58) v1(27.82,78.94) v1(28.45,79.58) v1(28.45,78.94) v1(42.04,82.88) v1(42.04,82.24) v1(42.04,81.61) v1(42.68,82.88) v1(42.68,82.24) v1(42.68,81.61) v1(48.14,119.2) v1(48.77,80.21) v1(48.77,79.58) v1(48.77,78.94) v1(49.03,119.2) v1(49.41,80.21) v1(49.41,79.58) v1(49.41,78.94) v1(49.91,121.23) v1(49.91,120.22) v1(49.91,119.2) v1(49.91,118.18) v1(49.91,117.17) v1(50.04,79.58) v1(50.04,78.94) v1(73.03,101.42) v1(73.42,104.72) v1(74.06,104.72) v1(74.43,101.42) v1(91.44,105.99) v1(91.44,105.23) v1(91.44,104.47) v1(91.44,103.71) v1(91.44,102.94) v1(92.08,106.75) v1(92.08,105.99) v1(92.08,105.23) v1(92.08,104.47) v1(92.08,103.71) v1(92.08,102.94)
1V35: length 42.4
  TOP w0.203: v1(47.88,123.52) 47.88,123.99 47.76,124.11 U14.1
  TOP w0.305: U2.H9 v2(63.76,120.55) ; U2.H2 v2(64.56,126.95) ; U2.C9 v2(68.56,120.55) ; U2.K2 v2(62.16,126.95) ; U2.K8 v2(62.16,121.35) ; U4.E4 v2(65.67,108.83) ; U2.C1 v2(68.56,127.75) ; U2.R1 v2(58.16,127.75) ; C60.1 71.76,109.95 v2(71.68,110.04) ; U4.J2 v2(61.67,110.43) ; U2.N9 60.16,120.95 v2(60.56,121.35) ; U4.M3 v2(59.27,109.63) ; U2.D2 v2(67.76,126.95) ; U2.E9 v2(66.16,120.55) ; U2.B2 v2(69.36,126.95) ; U2.A1 v2(70.16,127.75) ; U2.D9 v2(66.96,120.55) ; U2.N1 v2(59.76,127.75) ; v2(64.07,111.23) 64.07,111.23 U4.F1 ; 90.17,127.33 UNK1V35.1 89.41,126.56 ; U4.B3 v2(68.07,109.63) ; U2.F1 v2(66.16,127.75) ; U2.A8 v2(70.16,121.35) ; U2.G7 v2(65.36,122.95) ; U4.R4 v2(56.77,108.43) ; U2.R9 v2(58.96,121.35)
  TOP w0.406: C57.1 62.57,114.03 v2(62.07,114.03) ; C58.1 60.77,114.04 v2(60.27,114.04) ; C56.1 v1(54.36,107.15)
  TOP w0.635: 91.89,127.2 C151.1 92.52,126.5
  TOP w1.016: C100.1 75.43,126.44 ; C100.1 74.17,125.38 ; C100.1 72.91,126.44 ; 92.4,123.99 C145.1 ; C145.1 92.4,126.1 ; C145.1 91.49,125.04 ; 92.4,121.57 C148.1 ; C148.1 92.4,123.68 ; C148.1 91.49,122.63
  BOTTOM w0.203: v1(92.46,121.36) 92.84,120.98 R62.1
  BOTTOM w0.305: v2(68.56,120.55) 69.17,120.55 C87.1 ; v2(65.36,122.95) 64.84,122.95 C92.1 ; v2(66.16,127.75) 66.25,127.84 C95.1 ; v2(70.16,121.35) 70.24,121.27 C97.1 ; v2(61.67,110.43) 62.17,110.43 R41.2 ; v2(63.76,120.55) 63.84,120.63 C91.1 ; v2(58.16,127.75) 58.07,127.84 C96.1 ; v2(58.96,121.35) 58.65,121.35 C86.1 ; C89.1 62.76,126.35 v2(62.16,126.95) ; C94.1 68.38,127.93 v2(68.56,127.75) ; C88.1 70.16,128.35 v2(70.16,127.75) ; UNK1V35.1 v1(90.55,127.33) ; C61.1 56.06,108.23
  BOTTOM w0.406: C59.1 61.66,110.44 v2(61.67,110.43) ; v2(64.07,111.23) 64.07,111.23 64.07,111.64 C55.1 ; 56.06,108.23 56.27,108.43 v2(56.77,108.43)
  vias: v1(72.65,126.82) v1(72.65,125.8) v1(73.66,125.17) v1(74.68,125.17) v1(90.55,126.69) v1(90.55,126.06) v1(90.55,125.42) v1(90.55,124.79) v1(90.55,124.15) v1(91.19,127.33) v1(91.19,126.69) v1(91.19,126.06) v1(91.19,125.42) v1(91.19,124.79) v1(91.19,124.15) v2(64.65,115.45) v2(64.65,114.85)
GND: length 526.8
  TOP w0.152: v2(35.29,103.96) 36.88,103.96 U5.H7 ; U5.C7 40.88,103.96 v2(37.69,103.96)
  TOP w0.203: 111,105.86 D1.A 110.6,106.23 110.37,105.99 v1(110.37,105.86) ; 109.86,107.9 D2.A 109.51,107.53 v1(109.24,107.81) ; U5.L8 34.67,102.97 34.67,103.35 U5.L7 ; v2(48.39,125.42) 48.28,125.31 U14.4 46.89,125.31 U14.PAD ; U14.8 44.83,124.91
  TOP w0.305: U4.E8 65.27,105.23 v2(64.87,105.63) U4.E7 ; 90.11,97.53 C164.2 ; C164.2 90.81,97.99 v1(91.06,98.24) ; C164.2 90.11,98.45 ; U5.K1 v2(35.28,108.76) U5.L1 ; R49.1 31.06,106.96 ; R49.1 30.65,106.5 ; R49.1 31.06,106.04 ; C62.1 45.91,123.34 ; C62.1 46.32,122.88 ; C62.1 45.91,122.42 ; U5.M5 v2(33.68,104.76) U5.M6 ; 41.72,137.11 GND#2.1 ; GND#2.1 43.88,137.11 ; GND#2.1 42.8,138.19 ; GND#2.1 42.8,136.03 ; v1(79.67,105.41) 79.34,105.74 v1(74.78,105.74) v1(73.68,105.74) 71.12,105.74 v1(70.87,105.99) ; v2(72.48,110.04) 72.4,109.95 C60.2 ; C141.2 106.09,118.69 ; U5.G12 38.08,99.11 38.14,99.05 ; U4.C5 v2(67.27,107.23) ; U3.8 97.26,91.48 v2(97.3,91.44) ; U3.8 U3.7 ; U3.8 95.6,91.48 ; 58.96,128.06 v2(58.96,127.75) U2.P1 ; GND#3.1 85.09,128.53 ; GND#3.1 83.89,127.33 ; GND#3.1 86.3,127.33 ; GND#3.1 85.09,126.12 ; U5.F7 v2(39.28,103.16) ; U4.J5 v2(62.47,107.23) U4.H6 ; U5.L7 v2(35.29,103.96) ; Q1.2 111.85,90.57 ; Q1.2 112.81,89.81 ; Q1.2 110.9,89.81 ; Q1.2 111.85,89.05 ; 26.09,110.07 T1.1 ; T1.1 25.47,111.16 ; T1.1 27.34,110.08 ; U5.B12 v2(42.48,99.16) ; U4.G13 v2(64.07,100.83) ; 34.49,98.38 v2(34.49,99.16) U5.L12 v2(34.49,99.96) U5.L11 v2(34.49,100.76) U5.L10 v2(34.49,101.56) U5.L9 v2(34.49,102.36) U5.L8 ; U5.C2 v2(41.68,107.96) U5.B2 ; v2(38.19,99.03) 38.16,99.05 38.14,99.05 ; 67.71,85.78 U11.4 v1(66.79,85.11) ; 38.38,97.76 v1(38.59,97.55) ; 38.38,97.76 C43.2 ; 38.38,97.76 38.41,97.76 ; 97.34,116.56 97.68,116.9 U6.19 ; 57.36,128.04 v2(57.36,127.75) U2.T1 ; U5.H2 v2(36.89,107.96) U5.J2 ; U5.G1 v2(37.68,108.76) ; U2.T9 v2(57.36,120.55) 57.36,120.39 ; C43.2 38,97.03 C45.2 ; C43.2 38,98.97 38.09,99.05 38.14,99.05 ; 97.49,97.09 C13.2 ; C13.2 98.61,97.09 ; C13.2 98.05,97.65 ; C58.2 61.43,114.93 ; C58.2 60.87,115.49 ; C58.2 60.31,114.93 ; U4.D2 v2(66.47,110.43) ; U4.G3 v2(64.07,109.63) ; U4.F10 v2(64.87,103.23) ; U5.H3 v2(36.89,107.16) ; U6.22 98.14,115.81 ; U6.22 97.48,115.4 97.34,115.54 ; U6.22 98.84,115.4 ; C12.2 53.67,83.45 ; C12.2 53.22,83.04 ; C12.2 52.59,83.45 v1(52.58,83.44) U7.6 50.11,83.44 v2(49.79,83.77) ; C167.2 73.98,88.34 v1(74.16,88.52) ; C167.2 73.98,87.44 ; C167.2 74.39,87.89 ; 76.46,77.26 P1.9 ; U6.1 103.35,114.4 v1(103.89,113.87) ; R75.2 110.67,85.85 ; R75.2 110.11,86.41 ; R75.2 109.55,85.85 ; 116.57,99.46 S1.4 115.79,100.41 ; U5.L3 v2(34.49,107.16) ; U5.H6 v2(36.89,104.76) ; U5.F9 v2(39.28,101.56) ; U5.L2 v2(35.28,107.96) U5.K2 ; U4.K4 v2(60.87,108.83) ; U4.E5 v2(65.67,108.03) ; 60.56,128.06 v2(60.56,127.75) U2.M1 ; C18.2 50.04,89.06 ; U2.G8 v2(65.36,122.15) ; C79.2 49.66,128.85 ; C79.2 48.81,128.05 ; C79.2 50.51,128.05 ; U4.E9 v2(65.67,104.03) ; U5.H10 v2(37.69,101.56) ; R61.1 106.74,114.39 ; R61.1 105.62,114.39 ; R61.1 106.18,113.83 ; 22.34,102.15 T5.2 ; 26.11,112.26 T1.2 27.98,111.18 ; 115.79,94.91 S1.3 116.57,95.86 ; U5.F1 v2(39.28,108.76) U5.E1 ; C2.2 32.08,83.45 ; C2.2 31,83.45 v1(30.99,83.44) U1.6 28.52,83.44 v2(28.2,83.77) ; C2.2 31.63,83.04 ; 105.21,114.39 R53.1 104.65,113.83 ; 100.16,87.39 C8.2 99.7,86.98 ; U5.F11 v2(39.28,99.96) ; R9.2 80.14,110.02 ; R9.2 79.68,109.61 ; R9.2 80.6,109.61 ; 23.42,100.24 T5.1 ; C33.2 39.75,88.97 v1(39.5,88.72) ; U5.H7 v2(37.69,103.96) ; U2.G1 v2(65.36,127.75) ; U2.B9 v2(68.56,121.35) ; U5.H5 v2(36.89,105.56) ; U2.E2 v2(66.96,126.95) ; U4.P2 v2(57.67,110.43) ; U2.E8 v2(66.96,121.35) ; U2.J2 v2(63.76,126.96) ; v2(41.68,99.16) U5.C12 v2(41.68,99.96) U5.C11 v2(41.68,100.76) U5.C10 v2(41.68,101.56) U5.C9 v2(41.68,102.36) U5.C8 v2(41.68,103.16) U5.C7 ; U5.A2 v2(43.28,107.96) ; 63.92,88.27 C166.1 ; C122.2 34.64,87.96 ; C45.2 38.18,96.3 ; C45.2 38.74,96.86 ; U5.H9 v2(37.69,102.36) ; U5.F3 v2(39.28,107.16) ; U2.P9 v2(58.96,120.55) 58.96,120.11 ; U3.7 98,92.13 v2(98.32,92.45) 98,92.78 U3.6 ; U3.7 U3.6 ; U3.7 95.6,92.13 ; GND#4.1 103.13,79.89 ; GND#4.1 101.92,78.69 ; GND#4.1 103.13,77.48 ; GND#4.1 104.33,78.69 ; 53.05,108.14 C56.2 ; C56.2 53.61,108.7 ; C56.2 54.17,108.14 ; C6.2 28.45,89.06 ; 56.83,85.88 U12.3 56.15,86.29 ; 39.03,84.15 C25.2 ; v1(85.77,107.77) C163.1 86.3,108.23 ; U5.C4 v2(41.68,106.36) ; U5.A5 v2(43.39,105.16) ; U2.G9 v2(65.36,120.55) ; U4.D12 v2(66.47,101.63) ; U2.E1 v2(66.96,127.75) ; U4.R9 v2(56.79,104.43) ; U4.L5 v2(60.07,108.03) ; U5.G10 v2(38.49,101.56) ; U2.M9 60.96,120.95 v2(60.56,120.55) ; U2.B1 v2(69.36,127.75) ; U4.M8 v2(59.27,105.63) ; 80.71,106.04 C46.2 ; C46.2 80.71,107.07 v1(80.78,107.13) ; C46.2 81.12,106.5 ; v2(68.87,111.23) U4.A1 ; U2.J8 v2(63.76,121.35) ; C1.2 v1(29.72,80.34) ; U5.A6 v2(43.39,104.36) ; U4.L1 v2(60.47,111.33) ; U3.6 U3.5 ; U3.6 95.6,92.78 ; 32.43,96.21 C124.2 ; C124.2 32.83,95.75 ; C124.2 32.83,96.67 ; U5.J1 v2(36.89,108.76) U5.H1 ; U4.H10 v2(63.27,103.23) ; U5.A12 v2(43.28,99.16) ; C5.2 27.18,89.06 ; 95.6,93.43 U3.5 ; U3.5 96.35,93.86 ; U3.5 97.26,93.43 v2(97.3,93.47) ; U2.D8 v2(66.96,122.15) ; U5.D12 v2(40.88,99.16) ; 75.19,77.26 P1.7 ; C16.2 48.77,89.06 ; U4.K10 v2(60.87,103.23) ; 44.83,124.91 44.14,124.91 C84.2 43.44,125.1 v1(43.31,124.98) ; 84.89,104.44 Y1.2 ; Y1.2 85.64,103.63 ; Y1.2 85.64,105.24 ; C10.2 v1(51.31,80.34) ; U5.D1 v2(40.88,108.76) ; U4.P12 v2(57.67,101.63) ; 62.67,115.49 C57.2 62.11,114.93 ; 68.2,81.73 GND.1 ; GND.1 67.44,82.5 ; GND.1 68.2,83.26 ; GND.1 68.97,82.5 ; U4.J9 v2(61.67,104.83) ; U4.B8 v2(67.27,105.63) ; 110.9,83.14 Q4.2 ; Q4.2 111.85,82.38 ; Q4.2 111.85,83.91 ; Q4.2 112.81,83.14 ; U4.K7 v2(61.67,106.43) ; U13.B3 v2(82.16,118.18) ; U5.K12 v2(35.28,99.16) ; U5.M4 v2(33.68,106.36) ; U4.C15 v2(66.87,99.12) ; U6.19 98.14,116.49 ; U6.19 98.84,116.9 ; U4.N5 v2(58.47,108.03) ; U4.K14 v2(61.67,100.83) ; 28.86,110.68 T1.5 ; U5.B1 v2(41.68,108.76) U5.C1 ; U4.H8 62.87,105.23 v2(62.47,105.63) ; U5.A4 v2(43.39,105.96) ; U5.A1 v2(43.28,108.76) ; U2.A9 v2(70.16,120.55) ; U4.A11 v2(69.07,102.83) ; U4.G5 v2(64.07,108.03) ; U2.F9 v2(65.36,121.35) ; U2.B3 v2(69.36,125.35) ; U4.N15 v2(58.87,99.13) ; U2.D1 v2(67.76,127.75) ; U4.L11 v2(60.07,102.43)
  TOP w0.406: C58.2 60.77,114.84 v2(60.27,114.84) ; v2(62.07,114.73) 62.47,114.73 C57.2
  TOP w0.508: 64.97,92.47 C68.2 ; 35.27,85.58 C121.2 ; C121.2 36.07,86.43 ; C121.2 35.27,87.28 ; 57.89,84.53 C169.2 ; C169.2 58.44,85.11 ; C169.2 58.44,83.94 ; C143.1 v1(105.4,116.42) ; 76.01,108.24 Y2.2 76.81,108.99 ; 55.12,85.9 C170.2
  TOP w0.635: v1(25,100.88) T5.1 v1(22.12,100.88) ; v1(21.61,101.59) 22.12,102.1 23.36,102.1 T5.2 24.67,102.15 v1(25.02,101.8) 25.37,102.15 T5.5 ; v1(25.29,111.27) T1.1 v1(27.71,109.87) ; 44.39,86.18 C15.2 ; C15.2 45.03,86.88 ; C15.2 45.03,85.48 ; 39.56,87.13 C32.2 ; C32.2 38.93,87.83 ; C32.2 39.56,88.53 ; T1.5 28.43,110.92 ; C173.2 58.11,89.93 ; C173.2 58.11,88.53 ; C173.2 57.47,89.23 ; C4.2 25.66,89.93 ; C4.2 26.36,89.29 ; C4.2 24.96,89.29 ; C9.2 101.92,86.88 ; C9.2 101.22,86.24 ; C9.2 100.52,86.88 ; C14.2 47.95,89.29 ; C14.2 47.25,89.93 ; C14.2 46.55,89.29 ; v1(28.25,110.69) 28.14,111.09 T1.2 25.94,112.36 25.42,112.36 v1(25.25,112.19) ; 93.92,126.5 C151.2 94.56,127.2 ; 57.92,85.89 v1(57.92,86.94) 57.92,88 ; 38.93,82.24 C22.2 39.56,81.54 ; 22.8,86.18 C3.2 ; C3.2 23.44,85.48 ; C3.2 23.44,86.88
  TOP w0.762: 97.35,110.88 C135.2 96.71,111.58 ; C21.2 94.78,91.58 ; C21.2 93.73,92.48 ; C21.2 92.68,91.58 ; 45.98,117.8 C82.2 ; C82.2 46.78,118.65 ; C82.2 46.78,116.95 ; 97.35,109.1 C137.2 ; C137.2 97.35,110.5 ; C137.2 96.71,109.8 ; 69.18,91.58 C64.2 ; C64.2 70.44,90.52 ; C64.2 71.7,91.58 ; 45.98,120.6 C83.2 ; C83.2 46.78,119.74 ; C83.2 46.78,121.45 ; C100.2 75.43,129.23 ; C100.2 72.91,129.23 ; C100.2 74.17,130.29 ; 35.5,92.9 Y3.2 36.35,91.95 ; C20.2 89.7,91.58 ; C20.2 88.65,92.48 ; C20.2 87.6,91.58 ; C54.2 68.75,116.2 ; C54.2 68.75,113.69 ; C54.2 69.81,114.95 ; 96.46,122.5 C138.2 ; C138.2 97.1,123.2 ; C138.2 97.1,121.8 ; 96.46,120.72 C136.2 97.1,121.42 ; C17.2 92.24,91.58 ; C17.2 91.19,92.48 ; C17.2 90.14,91.58 ; 85.06,91.58 C19.2 ; C19.2 87.16,91.58 ; C19.2 86.11,92.48 ; 91.08,133.68 C157.2 ; C157.2 92.33,134.73 ; C157.2 93.59,133.68 ; C71.2 68.44,91.64 ; C71.2 67.19,90.59 ; C71.2 65.93,91.64 ; 46.68,126.65 C81.2 ; C81.2 46.68,128.76 ; C81.2 47.58,127.71 ; 46.49,125.92 U14.PAD v1(46.49,123.64)
  TOP w1.016: 94.3,123.68 C148.2 95.2,122.63 ; C145.2 95.2,125.04 ; C145.2 94.3,126.1 ; C145.2 94.3,123.99 ; C146.2 96.27,109.55 ; 102.45,86.62 C11.2 ; C11.2 104.56,86.62 ; C11.2 103.51,85.72
  TOP w1.27: 96.14,102.07 C149.2 ; C149.2 96.14,104.58 ; C149.2 97.2,103.32 ; 96.14,105.11 C150.2 ; C150.2 96.14,107.63 ; C150.2 97.2,106.37 ; 100.92,126.69 D3.A ; D3.A 102.11,125.29 ; D3.A 103.31,126.69
  L5_SIG w0.305: 85.09,126.12 GND#3.1 ; GND#3.1 86.3,127.33 ; GND#3.1 85.09,128.53 ; GND#3.1 83.89,127.33 ; 101.92,78.69 GND#4.1 ; GND#4.1 103.13,79.89 ; GND#4.1 104.33,78.69 ; GND#4.1 103.13,77.48 ; 68.2,81.73 GND.1 ; GND.1 68.97,82.5 ; GND.1 67.44,82.5 ; GND.1 68.2,83.26 ; GND#2.1 42.8,138.19 ; GND#2.1 42.8,136.03 ; GND#2.1 41.72,137.11 ; GND#2.1 43.88,137.11
  L6_SIG w0.305: 75.19,77.26 P1.7 ; GND.1 68.97,82.5 ; GND.1 68.2,81.73 ; GND.1 67.44,82.5 ; GND.1 68.2,83.26 ; 42.8,136.03 GND#2.1 ; GND#2.1 41.72,137.11 ; GND#2.1 42.8,138.19 ; GND#4.1 103.13,79.89 ; GND#4.1 104.33,78.69 ; GND#4.1 103.13,77.48 ; GND#4.1 101.92,78.69 ; 85.09,126.12 GND#3.1 ; GND#3.1 85.09,128.53 ; GND#3.1 83.89,127.33 ; GND#3.1 86.3,127.33 ; 76.46,77.26 P1.9 77.25,78.05
  BOTTOM w0.305: C119.2 62.89,98.41 v2(62.87,98.43) ; 38.18,97.79 C38.2 38.18,99.02 v2(38.19,99.03) 38,99.21 C44.2 ; 63.57,95.97 C105.2 64.13,96.53 ; R42.2 54.75,129.12 54.99,129.36 v1(55.38,129.36) ; v2(82.16,118.18) 82.13,118.21 C48.2 ; 53.61,105.03 C90.2 ; C90.2 54.17,105.59 ; C90.2 v2(54.17,104.44) C78.2 ; 102.28,118.06 R63.2 102.68,117.72 102.3,117.34 101.84,117.34 v2(101.81,117.37) ; 43.51,104.2 C31.2 44.07,104.76 ; 67.42,107.04 C178.2 67.98,106.48 ; C78.2 54.17,103.27 ; C78.2 53.61,103.83 ; R72.2 99.62,128.54 ; R72.2 100.37,127.98 ; R72.2 100.93,128.54 ; 34.48,110.31 C29.2 33.92,109.76 ; C96.2 57.44,127.83 v2(57.36,127.75) ; C44.2 38.41,99.56 ; C44.2 38,100.02 ; 79.2,104.58 R15.2 ; R15.2 79.76,105.14 ; R15.2 79.81,104.53 C47.2 80.78,104.94 ; C48.2 81.65,118.62 ; C48.2 81.19,118.21 ; 55.97,101.22 55.97,101.22 C112.2 56.06,100.54 v2(56.06,100.03) 56.06,99.52 C114.2 ; 64.3,122.23 C92.2 ; C92.2 65.22,122.23 ; C92.2 64.76,121.83 ; v2(63.76,121.35) 63.84,121.27 C91.2 ; 67.11,96.53 C113.2 ; C113.2 67.67,95.97 ; C113.2 v2(68.37,96.53) C107.2 ; 63.17,103.27 C74.2 ; C74.2 63.17,104.39 ; C74.2 62.61,103.83 ; 86.38,100.07 R77.2 86.38,98.95 ; v2(41.68,101.56) 41.77,101.48 C40.2 41.77,100.84 v2(41.68,100.76) ; 69.07,103.17 C69.2 69.63,103.73 ; 48.31,127.39 C80.2 48.77,127.8 ; 65.77,104.17 C75.2 66.33,104.73 ; GND#2.1 42.8,138.19 ; GND#2.1 43.88,137.11 ; GND#2.1 42.8,136.03 ; GND#2.1 41.72,137.11 ; C30.2 40.99,97.66 ; C30.2 40.43,98.22 ; C30.2 40.43,97.1 ; 69.27,122.01 C87.2 68.71,121.45 ; C156.2 97.46,128.45 ; C156.2 97.46,127.07 ; C156.2 96.91,127.89 ; 61.07,95.97 C67.2 ; 53.61,102.23 C108.2 ; C108.2 54.17,101.67 ; C108.2 v2(54.17,102.83) ; 60.51,111.43 C59.2 61.07,111.99 ; 30.18,98.31 C129.1 29.72,97.9 ; 66.92,111.33 C99.1 66.46,110.92 ; C28.2 39.39,110.02 ; 34.16,107.26 34.16,107.28 ; 34.16,107.28 34.37,107.28 v2(34.49,107.16) 34.55,107.1 C41.2 34.09,106.69 ; 34.16,107.28 C24.2 33.76,107.76 ; 77.36,118.51 R120.2 ; C36.2 33.58,104.73 ; C36.2 33.02,104.17 ; C36.2 32.46,104.73 ; 75.19,77.26 P1.7 ; 100.92,118.07 C139.1 ; C139.1 101.48,117.51 ; C139.1 102.04,118.07 ; R2.1 97.21,96.2 ; R2.1 v1(96.65,96.97) ; R2.1 96.09,96.2 ; R90.2 92.35,115.81 ; R90.2 92.91,115.27 ; R90.2 91.79,115.27 ; 63.27,104.98 C70.2 62.71,105.54 ; v1(62.26,116.75) R165.2 ; v1(103.13,111.64) C7.1 102.37,111.24 ; R3.1 100,94.45 ; R3.1 99.44,93.89 ; R3.1 98.89,94.45 ; GND.1 68.2,83.26 ; GND.1 67.44,82.5 ; GND.1 68.2,81.73 ; GND.1 68.97,82.5 ; 103,115.22 R54.2 102.44,115.78 ; 58.71,99.71 C118.2 59.17,99.3 ; 61.26,104.49 C72.2 61.82,103.93 ; 64.62,96.71 C117.2 ; C117.2 65.5,96.71 v2(65.68,96.53) ; C117.2 65.07,96.3 ; v2(41.68,102.36) 41.77,102.44 C27.2 41.77,103.08 v2(41.68,103.16) ; 83.89,127.33 GND#3.1 ; GND#3.1 85.09,126.12 ; GND#3.1 85.09,128.53 ; GND#3.1 86.3,127.33 ; v2(67.76,127.75) 67.75,127.76 C94.2 67.34,128.36 ; 68.97,102.73 v2(69.07,102.83) ; 68.97,102.73 69,102.73 ; 68.97,102.73 C162.2 68.59,102.27 ; R65.1 102.49,114.79 ; R65.1 101.93,114.23 ; R65.1 103.05,114.23 ; 101.92,78.69 GND#4.1 ; GND#4.1 104.33,78.69 ; GND#4.1 103.13,79.89 ; GND#4.1 103.13,77.48 ; 43.79,98.83 C128.2 ; 83.77,99.53 C154.2 84.33,98.97 ; C107.2 69.63,96.53 ; C107.2 69.07,95.97 ; 79.68,109.29 C174.2 79.12,109.85 ; v2(40.88,108.76) 40.59,108.46 C23.2 ; 57.21,102.33 C116.2 57.76,101.77 ; C91.2 64.82,121.27 ; C91.2 64.36,121.68 ; 66.84,96.53 C115.2 66.28,95.97 ; R119.2 77.36,120.65 ; v2(36.89,107.96) 36.7,107.96 C39.2 ; 76.46,77.26 P1.9 77.25,78.05 ; 37.73,110.56 C126.1 38.84,110.56 ; v2(66.96,127.75) 66.88,127.83 C95.2 67.29,128.36 ; 91.94,129.43 C155.2 92.5,128.66 ; 59.87,95.97 C106.2 ; C111.2 68.63,99.13 ; C111.2 68.07,98.57 ; C111.2 67.51,99.13 ; C55.2 64.27,113.39 ; C55.2 64.83,112.83 ; C55.2 63.71,112.83 ; v2(61.67,112.94) 62.17,112.94 R40.2 ; v2(69.36,127.75) 69.36,128.37 C88.2 ; v2(58.96,120.55) 58.46,120.55 C86.2 58.06,120.55 v2(57.36,120.55) ; C42.2 41.68,106.54 v2(41.68,106.36) ; v2(70.16,120.55) 70.24,120.63 C97.2 70.77,120.23 ; 51.96,128.93 C101.2 ; C101.2 51.4,129.49 ; C101.2 51.96,130.05 ; 64.61,99.61 C161.2 65.07,99.2 ; C114.2 55.97,99.99 ; C114.2 55.97,98.87 ; 69.79,106.88 C52.2 ; 65.3,127.76 C63.1 64.89,128.22 ; 81.61,121.98 R116.2 82.73,121.98 ; 62.17,95.97 C109.2 ; 69.79,106.79 C53.2 70.19,106.33 ; 61.81,113.13 R40.2 ; R40.2 62.93,113.13 ; v2(60.56,120.55) 61.04,121.03 C102.2 ; U10.4 v1(97.29,129.93) ; 55.64,106.68 C51.2 55.08,106.12 ; C34.2 36.98,110.02 ; 104.11,113.61 C147.1 104.66,113.05 ; 46.24,98.25 C127.2 45.68,97.69 ; 85.35,103.49 C140.2 v1(86.11,102.93) ; R121.2 80.7,115.4 ; 60.07,99.37 C110.2 ; C165.2 88.37,95.02 ; C165.2 86.67,95.02 ; C165.2 87.52,94.22 ; 57.67,104.51 C120.2 57.21,104.92 ; 85.35,98.97 C168.2 ; 56.06,107.01 C61.2 ; v2(39.28,107.16) C125.1 ; C142.1 106.21,115.64 ; 42.49,105.7 C37.2 43.05,106.26 ; v2(63.76,126.96) 63.76,126.45 C89.2 63.86,125.79 ; 62.56,107.47 C73.2 ; C26.2 40.31,98.56
  BOTTOM w0.406: C66.2 62.37,101.53 v2(61.67,100.83) ; v2(43.28,99.16) 43.36,99.24 C128.2 ; C67.2 v2(60.47,96.53) C106.2 ; C105.2 v2(62.88,96.53) C109.2 ; C115.2 v2(65.68,96.53) ; C127.2 v1(45.68,99.05) ; C50.2 71.57,102.83 v2(71.57,102.83) C159.2 v2(71.57,101.62) C160.2 ; v2(60.87,103.23) 61.17,103.53 61.17,103.83 C72.2 ; C59.2 60.97,111.33 v2(60.47,111.33) ; C28.2 39.28,109.35 v2(39.28,108.76)
  BOTTOM w0.508: v1(79.12,111.45) 78.81,111.14 R91.2 ; v1(105.4,116.42) 105.66,116.16 C142.1 ; C29.2 v1(35.18,109.76) ; 38.28,111.36 C126.1 ; v1(82.17,122.76) R116.2 ; v1(76.58,119.07) R120.2 ; v2(36.89,108.76) 36.89,109.37 C34.2 ; v1(80.14,114.63) R121.2 ; C35.2 v1(44.99,101.75) ; v1(76.58,120.09) R119.2
  BOTTOM w0.635: 80.27,111.83 E6.1 ; E6.1 81.1,112.72 ; E6.1 80.27,113.61 ; C153.2 95.44,104.47 ; C153.2 94.81,105.17 ; C153.2 94.81,103.77 ; 94.81,105.29 C152.2 ; C152.2 94.81,106.69 ; C152.2 95.44,105.99 ; C85.2 74.23,107.83 v1(75.48,107.83)
  BOTTOM w0.762: 76.58,98.51 76.58,99.77 ; 76.58,99.77 77.64,99.77 ; 76.58,99.77 76.58,101.03 ; 28.32,96.15 C130.2 ; C130.2 27.63,96.78 ; C130.2 29.02,96.78 ; 50.25,102.25 C77.2 ; C77.2 49.35,103.3 ; C77.2 50.25,104.36 ; C104.2 55.16,94.88 ; C104.2 54.11,93.98 ; C104.2 53.05,94.88 ; 57.03,93.98 C65.2 ; C65.2 58.08,94.88 ; C65.2 55.97,94.88 ; 76.58,101.94 76.58,103.2 ; 76.58,103.2 76.58,104.45 ; 76.58,103.2 77.64,103.2 ; 70.97,96.47 C103.2 72.03,97.37 ; C76.2 49.76,108.89 ; C76.2 49.76,106.38 ; C76.2 48.71,107.63
  vias: v1(10.14,96.59) v1(10.11,93.06) v1(10.96,120.04) v1(11.13,116.51) v1(11.13,93.06) v1(11.41,96.59) v1(11.69,130.12) v1(11.69,125.04) v1(11.69,111.07) v1(11.69,105.99) v1(11.69,88.21) v1(11.69,83.13) v1(12.23,120.04) v1(12.4,116.51) v1(12.4,93.06) v1(12.68,96.59) v1(13.5,120.04) v1(13.67,116.51) v1(13.67,93.06) v1(13.95,96.59) v1(14.23,127.58) v1(14.23,108.53) v1(14.23,103.45) v1(14.23,85.67) v1(14.23,80.59) v1(14.77,120.04) v1(14.94,116.51) v1(14.94,93.06) v1(15.22,96.59) v1(16.04,120.04) v1(15.98,93.06) v1(16.21,116.51) v1(16.46,96.85) v1(16.77,130.12) v1(16.77,125.04) v1(16.77,111.07) v1(16.77,105.99) v1(16.77,88.21) v1(16.77,83.13) v1(16.77,78.05) v1(17.18,100.43) v1(17.18,99.16) v1(17.18,97.89) v1(17.24,93.26) v1(17.31,120.04) v1(17.37,101.69) v1(17.48,116.49) v1(17.88,102.85) v1(18.37,93.84) v1(18.57,119.88) v1(18.65,116) v1(18.67,103.84) v1(19.31,127.58) v1(19.31,122.5) v1(19.31,113.61) v1(19.31,108.53) v1(19.31,94.7) v1(19.31,90.75) v1(19.31,85.67) v1(19.31,80.59) v1(19.76,119.43) v1(19.75,115.36) v1(19.7,104.59) v1(20.11,95.68) v1(20.59,96.86) v1(20.75,100.66) v1(20.71,99.39) v1(20.71,98.12) v1(20.86,118.8) v1(20.85,114.73) v1(20.88,105.05) v1(21.85,111.07) v1(21.85,93.29) v1(21.85,88.21) v1(21.85,83.13) v1(21.85,78.05) v1(21.96,118.16) v1(21.95,114.09) v1(22.15,105.18) v1(22.61,86.18) v1(22.74,99.9) v1(23.06,117.53) v1(23.05,113.46) v1(23.42,105.18) v1(23.63,87.2) v1(24.01,99.9) v1(24.16,116.89) v1(24.15,112.82) v1(24.39,122.5) v1(24.39,95.83) v1(24.39,90.75) v1(24.39,75.51) v1(24.64,89.23) v1(24.69,105.18) v1(25.26,116.26) v1(25.28,99.9) v1(25.4,110.18) v1(25.66,90.24) v1(25.96,105.18) v1(26.17,99.39) v1(26.36,115.62) v1(26.55,109.55) v1(26.55,89.35) v1(26.93,119.96) v1(27.23,105.18) v1(27.18,96.59) v1(27.46,114.99) v1(27.44,99.39) v1(27.56,89.35) v1(27.69,108.66) v1(28.32,107.77) v1(28.32,95.58) v1(28.45,99.39) v1(28.56,114.35) v1(28.5,105.18) v1(28.58,89.35) v1(29.21,107.26) v1(29.47,132.66) v1(29.47,122.5) v1(29.47,117.42) v1(29.47,96.59) v1(29.47,90.75) v1(29.47,75.51) v1(29.72,113.61) v1(29.72,97.61) v1(30.36,107.13) v1(30.99,112.85) v1(31.75,91.26) v1(32.01,119.96) v1(32.01,111.96) v1(32.01,88.21) v1(32.01,78.05) v1(32.13,96.21) v1(32.26,107.26) v1(33.02,110.56) v1(33.4,109.55) v1(34.55,132.66) v1(34.55,122.5) v1(34.55,75.51) v1(34.93,85.16) v1(35.06,87.96) v1(35.18,93.16) v1(35.82,119.96) v1(36.33,87.96) v1(36.33,86.69) v1(36.58,91.64) v1(37.79,111.36) v1(38.19,96.06) v1(38.74,88.72) v1(38.74,87.83) v1(38.74,86.94) v1(38.74,84.53) v1(38.74,83.39) v1(38.74,82.62) v1(38.74,81.86) v1(39.63,132.66) v1(39.63,86.94) v1(39.63,79.32) v1(40.43,96.92) v1(44.2,86.18) v1(45.22,87.2) v1(45.47,117.8) v1(45.6,121.1) v1(45.6,120.09) v1(46.1,119.2) v1(46.36,128.98) v1(46.36,126.44) v1(46.36,89.35) v1(46.99,121.87) v1(46.99,119.2) v1(46.99,116.41) v1(47.25,128.98) v1(47.25,126.44) v1(47.88,128.22) v1(47.88,127.2) v1(48.14,89.35) v1(49.03,89.35) v1(49.41,109.17) v1(49.66,106.12) v1(50.04,89.35) v1(50.3,114.88) v1(50.3,112.98) v1(50.93,111.45) v1(51.18,121.74) v1(51.69,128.72) v1(51.69,127.96) v1(51.95,123.14) v1(52.45,110.69) v1(53.56,81.11) v1(54.23,85.67) v1(54.37,107.9) v1(55.12,85.67) v1(55.76,132.66) v1(56.01,85.67) v1(56.14,79.32) v1(57.36,85.11) v1(57.92,88.21) v1(57.92,85.67) v1(58.36,83.61) v1(63.76,81.86) v1(64.15,88.9) v1(64.65,92.15) v1(65.66,92.15) v1(65.66,91.13) v1(66.3,137.74) v1(66.3,132.66) v1(66.3,79.32) v1(68.84,135.2) v1(68.79,92.09) v1(68.79,91.07) v1(70.57,96.32) v1(71.38,137.74) v1(71.38,132.66) v1(71.37,96.32) v1(71.96,92.09) v1(71.96,91.07) v1(72.65,129.87) v1(72.65,128.85) v1(73.66,130.5) v1(73.92,135.2) v1(74.68,130.5) v1(75.19,119.96) v1(75.95,104.72) v1(75.95,101.42) v1(76.46,137.74) v1(76.46,132.66) v1(76.46,122.5) v1(76.97,104.72) v1(76.97,101.42) v1(77.74,101.42) v1(77.98,104.72) v1(79,135.2) v1(79,130.12) v1(79,125.04) v1(79.25,110.31) v1(80.14,111.45) v1(80.14,110.31) v1(80.68,105.41) v1(81.54,137.74) v1(81.54,132.66) v1(81.54,127.58) v1(81.54,79.32) v1(82.68,82.62) v1(82.68,81.73) v1(84.08,118.44) v1(84.59,92.15) v1(84.59,91.01) v1(85.62,92.82) v1(87.39,91.8) v1(87.38,91.01) v1(88.59,95.62) v1(88.65,92.91) v1(89.67,135.07) v1(89.67,134.06) v1(89.67,133.17) v1(89.89,95.62) v1(89.92,92.15) v1(89.92,91.13) v1(90.68,135.07) v1(90.68,134.06) v1(90.68,133.17) v1(91.19,92.91) v1(91.29,95.62) v1(91.7,137.74) v1(91.7,135.07) v1(92.46,92.15) v1(92.46,91.13) v1(92.71,135.07) v1(92.97,128.47) v1(93.22,96.34) v1(93.39,92.92) v1(93.48,100.15) v1(93.73,135.07) v1(94.87,127.33) v1(94.87,126.44) v1(95.13,116.41) v1(95.13,115.77) v1(95.13,108.28) v1(95.25,100.15) v1(95.25,98.12) v1(95.25,94.18) v1(95.25,93.16) v1(95.25,92.15) v1(95.25,91.13) v1(95.38,125.42) v1(95.38,124.41) v1(95.38,123.39) v1(95.38,122.5) v1(96.02,104.85) v1(96.14,123.39) v1(96.14,122.5) v1(96.14,121.61) v1(96.14,120.34) v1(96.14,116.41) v1(96.14,115.77) v1(96.4,111.83) v1(96.4,111.07) v1(96.4,110.31) v1(96.4,109.42) v1(96.4,108.66) v1(96.78,137.74) v1(96.78,104.85) v1(97.03,100.15) v1(97.16,123.39) v1(97.16,121.61) v1(97.16,116.41) v1(97.16,115.77) v1(97.29,108.91) v1(97.54,108.02) v1(97.54,107.13) v1(97.54,106.12) v1(97.54,105.1) v1(97.54,104.09) v1(97.54,102.94) v1(98.05,97.86) v1(98.23,127.07) v1(98.81,97.1) v1(99.57,100.15) v1(99.57,98.12) v1(100.46,126.95) v1(100.46,125.93) v1(101.35,100.15) v1(101.35,98.12) v1(101.48,124.91) v1(101.86,137.74) v1(102.49,124.91) v1(103.13,95.83) v1(103.38,100.15) v1(103.38,98.12) v1(103.51,127.96) v1(103.51,126.95) v1(103.51,125.93) v1(103.51,124.91) v1(104.46,111.64) v1(104.52,126.95) v1(104.52,124.91) v1(105.16,100.15) v1(105.16,98.12) v1(105.54,126.95) v1(105.67,97.1) v1(106.18,101.42) v1(106.43,118.69) v1(106.56,126.95) v1(106.62,113.17) v1(106.68,104.47) v1(106.68,102.94) v1(106.94,98.88) v1(107.7,85.67) v1(108.21,100.15) v1(108.21,95.83) v1(109.22,101.42) v1(109.48,104.47) v1(109.48,102.94) v1(109.59,105.88) v1(110.52,92.4) v1(110.75,94.56) v1(110.75,86.94) v1(112.02,78.05) v1(114.56,88.21) v1(115.83,94.56) v1(116.34,100.78) v2(9.56,123.72) v2(9.56,122.71) v2(9.56,121.69) v2(9.56,114.96) v2(9.56,113.94) v2(9.56,112.93) v2(9.56,100.23) v2(9.56,99.21) v2(9.56,98.19) v2(9.56,91.46) v2(9.56,90.45) v2(9.56,89.43) v2(10.57,123.72) v2(10.57,122.71) v2(10.57,121.69) v2(10.57,114.96) v2(10.57,113.94) v2(10.57,112.93) v2(10.57,100.23) v2(10.57,99.21) v2(10.57,98.19) v2(10.57,91.46) v2(10.57,90.45) v2(10.57,89.43) v2(11.59,123.72) v2(11.59,122.71) v2(11.59,121.69) v2(11.59,114.96) v2(11.59,113.94) v2(11.59,112.93) v2(11.59,100.23) v2(11.59,99.21) v2(11.59,98.19) v2(11.59,91.46) v2(11.59,90.45) v2(11.59,89.43) v2(12.6,123.72) v2(12.6,122.71) v2(12.6,121.69) v2(12.6,114.96) v2(12.6,113.94) v2(12.6,112.93) v2(12.6,100.23) v2(12.6,99.21) v2(12.6,98.19) v2(12.6,91.46) v2(12.6,90.45) v2(12.6,89.43) v2(13.62,123.72) v2(13.62,122.71) v2(13.62,121.69) v2(13.62,114.96) v2(13.62,113.94) v2(13.62,112.93) v2(13.62,100.23) v2(13.62,99.21) v2(13.62,98.19) v2(13.62,91.46) v2(13.62,90.45) v2(13.62,89.43) v2(27.39,84.58) v2(27.39,83.77) v2(27.39,82.95) v2(28.2,84.58) v2(28.2,82.95) v2(29.01,84.58) v2(29.01,83.77) v2(29.01,82.95) v2(48.98,84.58) v2(48.98,83.77) v2(48.98,82.95) v2(49.79,84.58) v2(49.79,82.95) v2(50.3,104.47) v2(50.3,102.05) v2(50.6,84.58) v2(50.6,83.77) v2(50.6,82.95) v2(52.84,95.07) v2(55.26,106.93) v2(55.5,95.07) v2(58.3,95.07) v2(64.97,112.73) v2(65.67,99.03) v2(68.56,123.75) v2(69.36,123.75) v2(69.47,116.33) v2(69.79,106.83) v2(70.16,114.95) v2(70.16,114.15) v2(83.87,98.83) v2(83.87,97.61) v2(83.87,96.39) v2(84.48,98.22) v2(84.48,97) v2(85.09,98.83) v2(85.09,97.61) v2(85.09,96.39) v2(85.7,98.22) v2(85.7,97) v2(86.31,98.83) v2(86.31,97.61) v2(86.31,96.39) v2(97.3,92.45) v2(98.32,93.47) v2(98.32,91.44) v2(99.34,93.47) v2(99.34,92.45) v2(99.34,91.44) v2(99.37,117.37) v2(99.37,116.15) v2(99.37,114.93) v2(99.98,116.76) v2(99.98,115.54) v2(100.59,117.37) v2(100.59,116.15) v2(100.59,114.93) v2(101.2,116.76) v2(101.2,115.54) v2(101.81,116.15) v2(101.81,114.93)
